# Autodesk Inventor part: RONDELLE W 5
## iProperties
Created: 2004-11
Part Number: RONDELLE W 5
Document SubType Name: Modeling
Designer: Bruno
Manufacturer: Standard
Standards Organization: Custom
Author: Bruno
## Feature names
1. Base1
